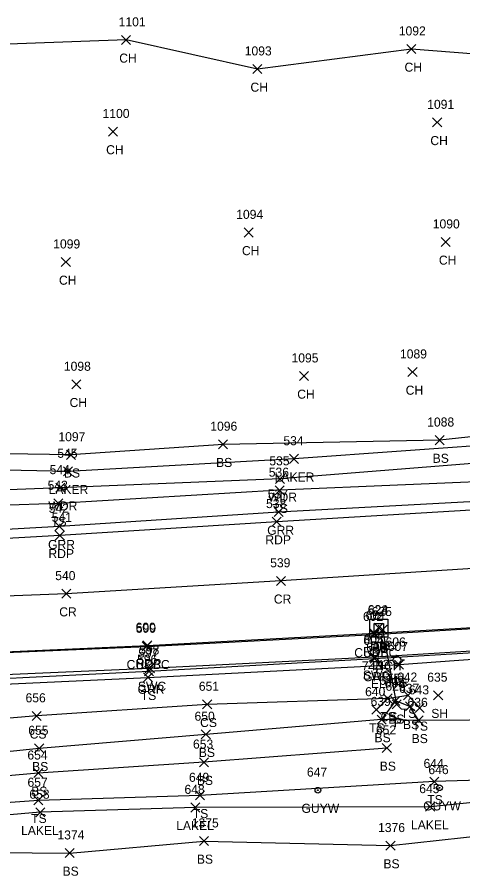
# Model space of a CAD drawing. Extents: x 1716490 to 1717645, y 888034 to 890004.
# Drawn here: x 1717260.6 to 1717358.9, y 888190.5 to 888379.8 of the extents above; entities that cross this region are included whole.
import ezdxf

# ---------------------------------------------------------------- set-up
doc = ezdxf.new("R2010")
doc.units = 0
for name, color, linetype in [('D_A', 7, 'Continuous'), ('D_C', 7, 'Continuous'), ('D_I', 7, 'Continuous'), ('D_TIC', 7, 'Continuous'), ('DCP', 7, 'Continuous'), ('DS', 7, 'Continuous'), ('L_A', 7, 'Continuous'), ('L_I', 7, 'Continuous'), ('L_TIC', 7, 'Continuous'), ('LAWA', 7, 'Continuous'), ('LAWE', 7, 'Continuous'), ('LELB', 7, 'Continuous'), ('LSOGP', 7, 'Continuous'), ('P_A', 7, 'Continuous'), ('P_I', 7, 'Continuous'), ('P_TIC', 7, 'Continuous'), ('PET', 7, 'Continuous'), ('PRC', 7, 'Continuous'), ('R_A', 7, 'Continuous'), ('R_I', 7, 'Continuous'), ('R_TIC', 7, 'Continuous'), ('RC', 7, 'Continuous'), ('RGR', 7, 'Continuous'), ('RSW', 7, 'Continuous'), ('U_A', 7, 'Continuous'), ('U_I', 7, 'Continuous'), ('UEPT', 7, 'Continuous'), ('UP', 7, 'Continuous'), ('UPGW', 7, 'Continuous')]:
    doc.layers.add(name, color=color, linetype=linetype)

msp = doc.modelspace()

# ---------------------------------------------------------------- linework, layer by layer
at = {"layer": 'D_TIC'}
for points in [[(1717339.35, 888244.19), (1717341.35, 888246.19)], [(1717341.35, 888244.19), (1717339.35, 888246.19)], [(1717340.21, 888243.77), (1717342.21, 888245.77)], [(1717342.21, 888243.77), (1717340.21, 888245.77)], [(1717343.3, 888227.29), (1717345.3, 888229.29)], [(1717345.3, 888227.29), (1717343.3, 888229.29)]]:
    msp.add_lwpolyline(points, dxfattribs=at)
at = {"layer": 'DCP'}
msp.add_lwpolyline([(1717341.21, 888244.77), (1717344.3, 888228.29)], dxfattribs=at)
at = {"layer": 'DS'}
for p, q in [((1717338.38, 888247.11), (1717342.38, 888247.11)), ((1717338.38, 888243.11), (1717338.38, 888247.11)), ((1717339.38, 888244.11), (1717339.38, 888246.11)), ((1717339.38, 888246.11), (1717341.38, 888246.11)), ((1717341.38, 888246.11), (1717341.38, 888244.11)), ((1717342.38, 888247.11), (1717342.38, 888243.11)), ((1717340.38, 888245.11), (1717340.38, 888245.11)), ((1717340.38, 888245.11), (1717340.38, 888245.11)), ((1717342.38, 888243.11), (1717338.38, 888243.11)), ((1717341.38, 888244.11), (1717339.38, 888244.11))]:
    msp.add_line(p, q, dxfattribs=at)
at = {"layer": 'L_TIC'}
for points in [[(1717283.62, 888373.82), (1717285.62, 888375.82)], [(1717285.62, 888373.82), (1717283.62, 888375.82)], [(1717346.56, 888371.82), (1717348.56, 888373.82)], [(1717348.56, 888371.82), (1717346.56, 888373.82)], [(1717312.58, 888367.41), (1717314.58, 888369.41)], [(1717314.58, 888367.41), (1717312.58, 888369.41)], [(1717352.26, 888355.63), (1717354.26, 888357.63)], [(1717354.26, 888355.63), (1717352.26, 888357.63)], [(1717280.72, 888353.61), (1717282.72, 888355.61)], [(1717282.72, 888353.61), (1717280.72, 888355.61)], [(1717310.69, 888331.36), (1717312.69, 888333.36)], [(1717312.69, 888331.36), (1717310.69, 888333.36)], [(1717354.15, 888329.26), (1717356.15, 888331.26)], [(1717356.15, 888329.26), (1717354.15, 888331.26)], [(1717270.32, 888324.84), (1717272.32, 888326.84)], [(1717272.32, 888324.84), (1717270.32, 888326.84)], [(1717322.89, 888299.7), (1717324.89, 888301.7)], [(1717324.89, 888299.7), (1717322.89, 888301.7)], [(1717346.82, 888300.58), (1717348.82, 888302.58)], [(1717348.82, 888300.58), (1717346.82, 888302.58)], [(1717272.66, 888297.86), (1717274.66, 888299.86)], [(1717274.66, 888297.86), (1717272.66, 888299.86)], [(1717305.03, 888284.64), (1717307.03, 888286.64)], [(1717307.03, 888284.64), (1717305.03, 888286.64)], [(1717352.83, 888285.56), (1717354.83, 888287.56)], [(1717354.83, 888285.56), (1717352.83, 888287.56)], [(1717271.45, 888282.32), (1717273.45, 888284.32)], [(1717273.45, 888282.32), (1717271.45, 888284.32)], [(1717320.69, 888281.44), (1717322.69, 888283.44)], [(1717322.69, 888281.44), (1717320.69, 888283.44)], [(1717270.81, 888278.67), (1717272.81, 888280.67)], [(1717272.81, 888278.67), (1717270.81, 888280.67)], [(1717317.58, 888277), (1717319.58, 888279)], [(1717319.58, 888277), (1717317.58, 888279)], [(1717269.11, 888275.06), (1717271.11, 888277.06)], [(1717271.11, 888275.06), (1717269.11, 888277.06)], [(1717317.52, 888274.5), (1717319.52, 888276.5)], [(1717319.52, 888274.5), (1717317.52, 888276.5)], [(1717268.66, 888271.61), (1717270.66, 888273.61)], [(1717270.66, 888271.61), (1717268.66, 888273.61)], [(1717343.86, 888236.07), (1717345.86, 888238.07)], [(1717345.86, 888236.07), (1717343.86, 888238.07)], [(1717288.45, 888233.25), (1717290.45, 888235.25)], [(1717290.45, 888233.25), (1717288.45, 888235.25)], [(1717345.81, 888229.31), (1717347.81, 888231.31)], [(1717347.81, 888229.31), (1717345.81, 888231.31)], [(1717352.48, 888229.29), (1717354.48, 888231.29)], [(1717354.48, 888229.29), (1717352.48, 888231.29)], [(1717301.51, 888227.29), (1717303.51, 888229.29)], [(1717303.51, 888227.29), (1717301.51, 888229.29)], [(1717341.32, 888228.58), (1717343.32, 888230.58)], [(1717343.32, 888228.58), (1717341.32, 888230.58)], [(1717341.32, 888228.58), (1717343.32, 888230.58)], [(1717343.32, 888228.58), (1717341.32, 888230.58)], [(1717343.04, 888228.04), (1717345.04, 888230.04)], [(1717345.04, 888228.04), (1717343.04, 888230.04)], [(1717338.85, 888226.1), (1717340.85, 888228.1)], [(1717340.85, 888226.1), (1717338.85, 888228.1)], [(1717346.26, 888226.83), (1717348.26, 888228.83)], [(1717348.26, 888226.83), (1717346.26, 888228.83)], [(1717348.42, 888226.49), (1717350.42, 888228.49)], [(1717350.42, 888226.49), (1717348.42, 888228.49)], [(1717263.9, 888224.74), (1717265.9, 888226.74)], [(1717265.9, 888224.74), (1717263.9, 888226.74)], [(1717339.99, 888223.94), (1717341.99, 888225.94)], [(1717341.99, 888223.94), (1717339.99, 888225.94)], [(1717339.99, 888223.94), (1717341.99, 888225.94)], [(1717341.99, 888223.94), (1717339.99, 888225.94)], [(1717348.19, 888223.75), (1717350.19, 888225.75)], [(1717350.19, 888223.75), (1717348.19, 888225.75)], [(1717348.19, 888223.75), (1717350.19, 888225.75)], [(1717350.19, 888223.75), (1717348.19, 888225.75)], [(1717301.22, 888220.68), (1717303.22, 888222.68)], [(1717303.22, 888220.68), (1717301.22, 888222.68)], [(1717264.44, 888217.58), (1717266.44, 888219.58)], [(1717266.44, 888217.58), (1717264.44, 888219.58)], [(1717341.15, 888217.66), (1717343.15, 888219.66)], [(1717343.15, 888217.66), (1717341.15, 888219.66)], [(1717300.79, 888214.53), (1717302.79, 888216.53)], [(1717302.79, 888214.53), (1717300.79, 888216.53)], [(1717264.25, 888212.13), (1717266.25, 888214.13)], [(1717266.25, 888212.13), (1717264.25, 888214.13)], [(1717351.66, 888210.27), (1717353.66, 888212.27)], [(1717353.66, 888210.27), (1717351.66, 888212.27)], [(1717299.92, 888207.21), (1717301.92, 888209.21)], [(1717301.92, 888207.21), (1717299.92, 888209.21)], [(1717264.27, 888206.12), (1717266.27, 888208.12)], [(1717266.27, 888206.12), (1717264.27, 888208.12)], [(1717298.91, 888204.55), (1717300.91, 888206.55)], [(1717300.91, 888204.55), (1717298.91, 888206.55)], [(1717350.71, 888204.71), (1717352.71, 888206.71)], [(1717352.71, 888204.71), (1717350.71, 888206.71)], [(1717264.68, 888203.48), (1717266.68, 888205.48)], [(1717266.68, 888203.48), (1717264.68, 888205.48)], [(1717300.8, 888197.15), (1717302.8, 888199.15)], [(1717302.8, 888197.15), (1717300.8, 888199.15)], [(1717341.96, 888196.13), (1717343.96, 888198.13)], [(1717343.96, 888196.13), (1717341.96, 888198.13)], [(1717271.16, 888194.5), (1717273.16, 888196.5)], [(1717273.16, 888194.5), (1717271.16, 888196.5)]]:
    msp.add_lwpolyline(points, dxfattribs=at)
at = {"layer": 'LAWA'}
msp.add_lwpolyline([(1717427.07, 888329.96), (1717424.15, 888313.24), (1717417.81, 888299.74), (1717405.98, 888286.01), (1717373.07, 888282.35), (1717318.58, 888278), (1717270.11, 888276.06), (1717231.85, 888274.55), (1717204.52, 888271.65)], dxfattribs=at)
at = {"layer": 'LAWE'}
for points in [[(1717421.68, 888328.92), (1717420.89, 888312.99), (1717415.11, 888301.4), (1717401.41, 888289.2), (1717371, 888285.95), (1717321.69, 888282.44), (1717271.81, 888279.67), (1717230.21, 888280.53), (1717194.5, 888279.04), (1717177.12, 888274.47), (1717174.06, 888271.23), (1717172.86, 888266.22)], [(1717428.73, 888210.05), (1717391.62, 888209.76), (1717351.71, 888205.71), (1717299.91, 888205.55), (1717265.68, 888204.48), (1717223.67, 888200.84), (1717208.56, 888201.76), (1717201.77, 888208.17), (1717191.38, 888215.04), (1717175.77, 888226.39)]]:
    msp.add_lwpolyline(points, dxfattribs=at)
at = {"layer": 'LELB'}
for points in [[(1717397.44, 888368.91), (1717401.94, 888364.63), (1717406.07, 888347.48), (1717411.38, 888343.28), (1717409.79, 888309.96), (1717403.02, 888297.91), (1717392.21, 888290.65), (1717353.83, 888286.56), (1717306.03, 888285.64), (1717272.45, 888283.32), (1717220.2, 888284.1), (1717193.83, 888280.31), (1717176.82, 888276.72), (1717169.82, 888270.77)], [(1717414.27, 888287.03), (1717406.99, 888281.7), (1717373.99, 888277.88), (1717318.52, 888275.5), (1717269.66, 888272.61), (1717230.91, 888271.26), (1717203.91, 888268.9), (1717185.06, 888265.29), (1717179.22, 888264.43), (1717179.32, 888261.72)], [(1717168.22, 888251.6), (1717169.76, 888223.63), (1717177.45, 888214.69), (1717194.47, 888204.09), (1717205.17, 888197.96), (1717222.8, 888195.9), (1717272.16, 888195.5), (1717301.8, 888198.15), (1717342.96, 888197.13), (1717391.28, 888202.44), (1717438.03, 888204.25)], [(1717195, 888228.65), (1717213.42, 888229.75), (1717254.51, 888232.62), (1717289.45, 888234.25), (1717344.86, 888237.07), (1717388.41, 888240.22), (1717429.71, 888242.89)], [(1717342.32, 888229.58), (1717302.51, 888228.29), (1717264.9, 888225.74), (1717212.77, 888221.26), (1717194.86, 888221.27), (1717182.07, 888225.99)], [(1717339.85, 888227.1), (1717342.32, 888229.58), (1717346.81, 888230.31), (1717349.42, 888227.49)], [(1717349.19, 888224.75), (1717347.26, 888227.83), (1717344.04, 888229.04), (1717340.99, 888224.94)], [(1717429.58, 888226.27), (1717393.83, 888225.01), (1717349.19, 888224.75), (1717340.99, 888224.94), (1717302.22, 888221.68), (1717265.44, 888218.58), (1717217.95, 888213.61)], [(1717342.15, 888218.66), (1717301.79, 888215.53), (1717265.25, 888213.13), (1717219.42, 888209.07), (1717204.97, 888210.23)], [(1717429.06, 888212.61), (1717392.81, 888212.48), (1717352.66, 888211.27), (1717300.92, 888208.21), (1717265.27, 888207.12), (1717222.12, 888203.99)]]:
    msp.add_lwpolyline(points, dxfattribs=at)
at = {"layer": 'LSOGP'}
msp.add_lwpolyline([(1717397.44, 888368.91), (1717347.56, 888372.82), (1717313.58, 888368.41), (1717284.61, 888374.82), (1717226.58, 888372.74), (1717200.46, 888359.46), (1717144.02, 888346.31), (1717139.03, 888337.96), (1717115.57, 888330.22), (1717057.48, 888334.02)], dxfattribs=at)
at = {"layer": 'P_TIC'}
for points in [[(1717316.86, 888267.58), (1717318.86, 888269.58)], [(1717318.86, 888267.58), (1717316.86, 888269.58)], [(1717269, 888264.54), (1717271, 888266.54)], [(1717271, 888264.54), (1717269, 888266.54)], [(1717317.78, 888254.52), (1717319.78, 888256.52)], [(1717319.78, 888254.52), (1717317.78, 888256.52)], [(1717270.43, 888251.69), (1717272.43, 888253.69)], [(1717272.43, 888251.69), (1717270.43, 888253.69)], [(1717338.42, 888242.96), (1717340.42, 888244.96)], [(1717340.42, 888242.96), (1717338.42, 888244.96)], [(1717288.28, 888240.31), (1717290.28, 888242.31)], [(1717290.28, 888240.31), (1717288.28, 888242.31)]]:
    msp.add_lwpolyline(points, dxfattribs=at)
at = {"layer": 'PET'}
msp.add_lwpolyline([(1717427.27, 888275.57), (1717374.24, 888271.92), (1717317.86, 888268.58), (1717270, 888265.54), (1717231.18, 888263.33), (1717177.06, 888260.69), (1717177.8, 888248.05), (1717178.6, 888236.51), (1717214.03, 888237.98), (1717254.52, 888239.74), (1717289.28, 888241.31), (1717339.42, 888243.96), (1717387.67, 888246.79), (1717419.3, 888248.63), (1717429.05, 888249.53)], dxfattribs=at)
at = {"layer": 'PRC'}
msp.add_lwpolyline([(1717428.93, 888262.88), (1717374.93, 888259.17), (1717318.78, 888255.52), (1717271.43, 888252.69), (1717231.27, 888251.09), (1717177.8, 888248.05)], dxfattribs=at)
at = {"layer": 'R_TIC'}
for points in [[(1717317.26, 888269.69), (1717319.26, 888271.69)], [(1717319.26, 888269.69), (1717317.26, 888271.69)], [(1717268.91, 888266.54), (1717270.91, 888268.54)], [(1717270.91, 888266.54), (1717268.91, 888268.54)], [(1717338.38, 888242.69), (1717340.38, 888244.69)], [(1717340.38, 888242.69), (1717338.38, 888244.69)], [(1717288.15, 888240.08), (1717290.15, 888242.08)], [(1717290.15, 888240.08), (1717288.15, 888242.08)], [(1717338.45, 888237.4), (1717340.45, 888239.4)], [(1717340.45, 888237.4), (1717338.45, 888239.4)], [(1717338.5, 888237.74), (1717340.5, 888239.74)], [(1717340.5, 888237.74), (1717338.5, 888239.74)], [(1717288.66, 888234.62), (1717290.66, 888236.62)], [(1717290.66, 888234.62), (1717288.66, 888236.62)], [(1717288.86, 888235.28), (1717290.86, 888237.28)], [(1717290.86, 888235.28), (1717288.86, 888237.28)]]:
    msp.add_lwpolyline(points, dxfattribs=at)
at = {"layer": 'RC'}
msp.add_lwpolyline([(1717178.77, 888236.27), (1717214.14, 888237.8), (1717254.52, 888239.57), (1717289.15, 888241.08), (1717339.38, 888243.69), (1717387.75, 888246.62), (1717419.31, 888248.49), (1717429.07, 888249.37)], dxfattribs=at)
at = {"layer": 'RGR'}
for points in [[(1717414.46, 888276.43), (1717374.09, 888273.7), (1717318.26, 888270.69), (1717269.91, 888267.54), (1717230.71, 888265.34), (1717183.33, 888262.06)], [(1717180.01, 888230.78), (1717185.31, 888230.2), (1717193.48, 888230.86), (1717213.85, 888231.84), (1717254.51, 888233.87), (1717289.66, 888235.62), (1717339.45, 888238.4), (1717388.12, 888241.37), (1717429.56, 888243.99)]]:
    msp.add_lwpolyline(points, dxfattribs=at)
at = {"layer": 'RSW'}
msp.add_lwpolyline([(1717178.7, 888235.76), (1717178.9, 888231.46), (1717213.38, 888232.72), (1717254.44, 888234.73), (1717289.86, 888236.28), (1717339.5, 888238.74), (1717388.22, 888241.81), (1717419.75, 888243.67), (1717429.73, 888244.54)], dxfattribs=at)
at = {"layer": 'UEPT'}
for p, q in [((1717340.26, 888238.55), (1717340.09, 888237.71)), ((1717339.26, 888236.05), (1717339.26, 888237.71)), ((1717339.26, 888237.71), (1717340.92, 888237.71)), ((1717340.09, 888236.88), (1717340.09, 888236.88)), ((1717340.92, 888237.71), (1717340.92, 888236.05)), ((1717340.92, 888236.05), (1717339.26, 888236.05)), ((1717339.84, 888235.21), (1717340.09, 888236.05))]:
    msp.add_line(p, q, dxfattribs=at)
at = {"layer": 'UP'}
for p, q in [((1717342.75, 888238.04), (1717343.58, 888238.04)), ((1717344.41, 888238.05), (1717344.41, 888238.05)), ((1717346.08, 888238.05), (1717345.24, 888238.05)), ((1717345.24, 888238.05), (1717345.24, 888238.05)), ((1717346.08, 888238.05), (1717346.08, 888238.05))]:
    msp.add_line(p, q, dxfattribs=at)
msp.add_circle((1717344.41, 888238.05), 0.833, dxfattribs=at)
at = {"layer": 'UPGW'}
for centre, radius in [((1717353.78, 888209.9), 0.625), ((1717326.93, 888209.36), 0.625), ((1717326.93, 888209.36), 0.0833), ((1717353.78, 888209.9), 0.0833)]:
    msp.add_circle(centre, radius, dxfattribs=at)

# ---------------------------------------------------------------- texts
at = {"layer": 'D_A'}
for s, p in [('DIB', (1717338.45, 888240.19)), ('DI', (1717339.44, 888240.11)), ('P', (1717340.59, 888239.77)), ('P', (1717343.68, 888223.29))]:
    msp.add_text(s, height=2, dxfattribs=at).set_placement(p)
at = {"layer": 'D_C'}
for s, p in [('7 INCH', (1717336.63, 888235.77)), ('2X2', (1717337.96, 888236.11))]:
    msp.add_text(s, height=2, dxfattribs=at).set_placement(p)
at = {"layer": 'D_I'}
for s, p in [('624', (1717337.94, 888248.19)), ('623', (1717337.97, 888248.11)), ('625', (1717338.81, 888247.77)), ('626', (1717341.84, 888231.29))]:
    msp.add_text(s, height=2, dxfattribs=at).set_placement(p)
at = {"layer": 'L_A'}
for s, p in [('CH', (1717283.11, 888369.82)), ('CH', (1717346.05, 888367.82)), ('CH', (1717312.06, 888363.41)), ('CH', (1717351.75, 888351.63)), ('CH', (1717280.21, 888349.61)), ('CH', (1717310.18, 888327.36)), ('CH', (1717353.64, 888325.26)), ('CH', (1717269.81, 888320.84)), ('CH', (1717322.38, 888295.7)), ('CH', (1717346.31, 888296.58)), ('CH', (1717272.15, 888293.86)), ('BS', (1717304.47, 888280.64)), ('BS', (1717352.27, 888281.56)), ('BS', (1717270.89, 888278.32)), ('LAKER', (1717317.39, 888277.44)), ('LAKER', (1717267.52, 888274.67)), ('WDR', (1717315.94, 888273)), ('WDR', (1717267.47, 888271.06)), ('TS', (1717316.93, 888270.5)), ('TS', (1717268.07, 888267.61)), ('TS', (1717343.27, 888232.07)), ('TS', (1717287.86, 888229.25)), ('TS', (1717345.22, 888225.31)), ('SH', (1717351.96, 888225.29)), ('CS', (1717300.95, 888223.29)), ('TS', (1717340.73, 888224.58)), ('CS', (1717340.76, 888224.58)), ('BS', (1717342.48, 888224.04)), ('TS', (1717338.26, 888222.1)), ('BS', (1717345.71, 888222.83)), ('TS', (1717347.83, 888222.49)), ('CS', (1717263.34, 888220.74)), ('BS', (1717339.43, 888219.94)), ('BS', (1717339.43, 888219.94)), ('BS', (1717347.63, 888219.75)), ('BS', (1717347.63, 888219.75)), ('BS', (1717300.66, 888216.68)), ('BS', (1717263.88, 888213.58)), ('BS', (1717340.59, 888213.66)), ('BS', (1717300.23, 888210.53)), ('BS', (1717263.69, 888208.13)), ('TS', (1717351.07, 888206.27)), ('TS', (1717299.33, 888203.21)), ('TS', (1717263.68, 888202.12)), ('LAKEL', (1717295.67, 888200.55)), ('LAKEL', (1717347.48, 888200.71)), ('LAKEL', (1717261.44, 888199.48)), ('BS', (1717300.24, 888193.15)), ('BS', (1717341.4, 888192.13)), ('BS', (1717270.6, 888190.5))]:
    msp.add_text(s, height=2, dxfattribs=at).set_placement(p)
at = {"layer": 'L_I'}
for s, p in [('1101', (1717282.98, 888377.82)), ('1092', (1717344.79, 888375.82)), ('1093', (1717310.8, 888371.41)), ('1091', (1717351.06, 888359.63)), ('1100', (1717279.43, 888357.61)), ('1094', (1717308.92, 888335.36)), ('1090', (1717352.29, 888333.26)), ('1099', (1717268.54, 888328.84)), ('1095', (1717321.12, 888303.7)), ('1089', (1717345.05, 888304.58)), ('1098', (1717270.89, 888301.86)), ('1088', (1717351.06, 888289.56)), ('1096', (1717303.2, 888288.64)), ('1097', (1717269.68, 888286.32)), ('534', (1717319.32, 888285.44)), ('545', (1717269.45, 888282.67)), ('535', (1717316.22, 888281)), ('544', (1717267.75, 888279.06)), ('536', (1717316.1, 888278.5)), ('543', (1717267.3, 888275.61)), ('607', (1717342.37, 888240.07)), ('596', (1717287.04, 888237.25)), ('642', (1717344.4, 888233.31)), ('635', (1717351.07, 888233.29)), ('651', (1717300.67, 888231.29)), ('641', (1717340.48, 888232.58)), ('641', (1717340.48, 888232.58)), ('638', (1717341.63, 888232.04)), ('637', (1717344.85, 888230.83)), ('640', (1717337.36, 888230.1)), ('643', (1717347.01, 888230.49)), ('656', (1717262.43, 888228.74)), ('639', (1717338.57, 888227.94)), ('639', (1717338.57, 888227.94)), ('636', (1717346.72, 888227.75)), ('636', (1717346.72, 888227.75)), ('650', (1717299.72, 888224.68)), ('655', (1717263.03, 888221.58)), ('652', (1717339.74, 888221.66)), ('653', (1717299.38, 888218.53)), ('654', (1717262.84, 888216.13)), ('644', (1717350.25, 888214.27)), ('657', (1717262.86, 888210.12)), ('649', (1717298.5, 888211.21)), ('648', (1717297.5, 888208.55)), ('645', (1717349.3, 888208.71)), ('658', (1717263.27, 888207.48)), ('1375', (1717299.11, 888201.15)), ('1376', (1717340.22, 888200.13)), ('1374', (1717269.47, 888198.5))]:
    msp.add_text(s, height=2, dxfattribs=at).set_placement(p)
at = {"layer": 'P_A'}
for s, p in [('RDP', (1717315.35, 888263.58)), ('RDP', (1717267.48, 888260.54)), ('CR', (1717317.22, 888250.52)), ('CR', (1717269.87, 888247.69)), ('RDP', (1717336.91, 888238.96)), ('RDP', (1717286.77, 888236.31))]:
    msp.add_text(s, height=2, dxfattribs=at).set_placement(p)
at = {"layer": 'P_I'}
for s, p in [('538', (1717315.5, 888271.58)), ('541', (1717268.2, 888268.54)), ('539', (1717316.41, 888258.52)), ('540', (1717268.98, 888255.69)), ('601', (1717337.5, 888246.96)), ('600', (1717286.71, 888244.31))]:
    msp.add_text(s, height=2, dxfattribs=at).set_placement(p)
at = {"layer": 'R_A'}
for s, p in [('GRR', (1717315.75, 888265.69)), ('GRR', (1717267.4, 888262.54)), ('CURBC', (1717334.96, 888238.69)), ('CURBC', (1717284.73, 888236.08)), ('SWC', (1717336.86, 888233.74)), ('GRR', (1717336.94, 888233.4)), ('SWC', (1717287.22, 888231.28)), ('GRR', (1717287.15, 888230.62))]:
    msp.add_text(s, height=2, dxfattribs=at).set_placement(p)
at = {"layer": 'R_I'}
for s, p in [('537', (1717315.89, 888273.69)), ('542', (1717267.54, 888270.54)), ('602', (1717336.89, 888246.69)), ('599', (1717286.78, 888244.08)), ('604', (1717336.96, 888241.4)), ('603', (1717337.01, 888241.74)), ('597', (1717287.3, 888238.62)), ('598', (1717287.49, 888239.28))]:
    msp.add_text(s, height=2, dxfattribs=at).set_placement(p)
at = {"layer": 'U_A'}
for s, p in [('TEL', (1717341.97, 888233.05)), ('EL', (1717338.63, 888231.88)), ('GUYW', (1717323.32, 888204.36)), ('GUYW', (1717350.18, 888204.9))]:
    msp.add_text(s, height=2, dxfattribs=at).set_placement(p)
at = {"layer": 'U_I'}
for s, p in [('606', (1717341.87, 888241.05)), ('605', (1717337.6, 888239.88)), ('647', (1717324.52, 888212.36)), ('646', (1717351.32, 888212.9))]:
    msp.add_text(s, height=2, dxfattribs=at).set_placement(p)

doc.saveas('drawing.dxf')
